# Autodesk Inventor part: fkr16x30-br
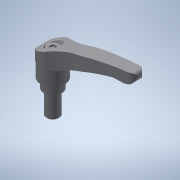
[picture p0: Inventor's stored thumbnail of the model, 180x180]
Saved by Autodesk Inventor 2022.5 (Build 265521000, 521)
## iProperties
Created: 2016-12
Part Number: fkr16x30-br
Material: 一般
Document SubType Name: Modeling
Designer: imaocorp
Density: 1 g/cm^3
Appearance: 既定
Author: imaocorp
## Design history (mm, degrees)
node "fkr16x30-br.x_t1"
node "K1000_516030_011"
node "Base1"
